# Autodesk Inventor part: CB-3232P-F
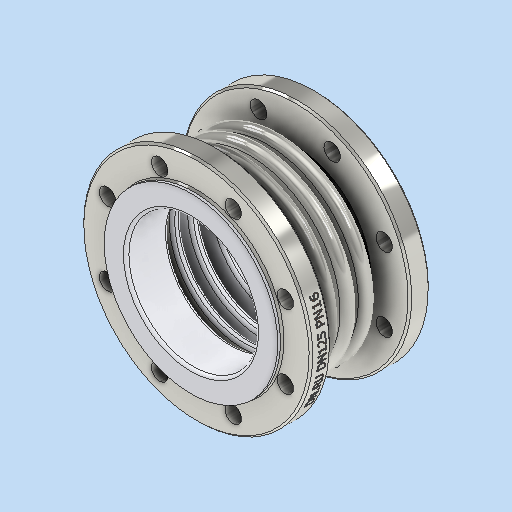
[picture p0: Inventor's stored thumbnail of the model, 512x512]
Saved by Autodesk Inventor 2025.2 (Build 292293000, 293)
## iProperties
Company: DN.RU
Created: 2026-04
Part Number: CB-3232P-F
Material: Типовые
Document SubType Name: Modeling
Designer: DN.RU
Density: 6.15933 g/cm^3
Appearance: По умолчанию
Description: D140-02142
Mass: 11200 g
Surface Area: 4913.79 cm^2
Volume: 1818.38 cm^3
Author: DN.RU
Title: Компенсатор сильфонный осевой DN.ru Ду125 Ру16
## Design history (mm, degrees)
sketch "Эскиз1"
  geometry: L1 (0, 0)-(0, -65); L2 (78.75, -65)-(78.75, 0); L3 (78.75, 0)-(0, 0); L4 (78.75, 0)-(78.75, 0); L5 (58.75, 0)-(98.75, 0); L6 (58.75, -7)-(98.75, -7); L7 (98.75, 7)-(58.75, 7); L8 (98.75, -5)-(58.75, -5); L9 (58.75, 5)-(98.75, 5); L10 (98.75, -13)-(58.75, -13); L11 (58.75, -15)-(98.75, -15); L12 (58.75, -20)-(98.75, -20); L13 (58.75, -27)-(98.75, -27); L14 (98.75, -25)-(58.75, -25); L15 (0, -65)-(78.75, -65); L16 (78.75, -65)-(70.75, -65); L17 (70.75, -65)-(70.75, -25); L18 (78.75, -15)-(76.75, -15); L19 (76.75, -15)-(76.75, -5); L20 (78.75, 5)-(76.75, 5); L21 (76.75, 5)-(76.75, 0); L22 (0, -65)-(0, -43); L23 (0, -43)-(125, -43); L24 (125, -43)-(125, -65); L25 (125, -65)-(0, -65); L26 (78.75, -43)-(78.75, -58); L27 (78.75, -58)-(82.75, -58); L28 (82.75, -58)-(82.75, -43); L29 (82.75, -43)-(78.75, -43); L30 (78.75, 0)-(105.75, 0); A1 r 7 centre (58.75, 0) between (58.75, 7) and (58.75, -7); A2 r 7 centre (98.75, 0) between (98.75, -7) and (98.75, 7); A3 r 5 centre (58.75, 0) between (58.75, 5) and (58.75, -5); A4 r 5 centre (98.75, 0) between (98.75, -5) and (98.75, 5); A5 r 5 centre (58.75, -20) between (58.75, -15) and (58.75, -25); A6 r 7 centre (58.75, -20) between (58.75, -13) and (58.75, -27); A7 r 5 centre (98.75, -20) between (98.75, -25) and (98.75, -15); A8 r 7 centre (98.75, -20) between (98.75, -27) and (98.75, -13); 20 further points
  constraints: 64 end point, 17 point on circle, 14 point on line, 8 centre point, 7 parallel, 5 perpendicular, 4 tangent, 3 midpoint, 2 vertical, 1 horizontal, 25 other
  dimensions: "d0" = 65 distance of L1.start L1.end; "d3" = 0 distance of L2.end L4.end; "d4" = 20 distance of L4.end L5.end; "d5" = 14 diameter of A2; "d6" = 2 distance between parallel lines of L6 L8; "d9" = 20 distance of L4.end point (78.75, -20); "d18" = 2 distance of L18.start L18.end; "d19" = 2 distance of L20.start L20.end; "d27" = 70.75 distance between parallel lines of L1 L17; "d28" = 8 distance between parallel lines of L2 L17; "d29" = 22 distance of L1.end L22.end; "d30" = 125 distance of L22.end L23.end; "d31" = 15 distance of L26.start L26.end; "d32" = 4 distance of L27.end L26.end
revolve "Вращение1" sketch "Эскиз1" stored, may be unused: angle "d20" = 360 deg
sketch "Эскиз3" dims "d33" = 210
  geometry: L1 (0, 0)-(71.096, 29.449); L2 (0, 0)-(76.954, 0); C1 r 9 at (97.007, 40.182); C2 r 9 at (40.182, 97.007); C3 r 9 at (-40.182, 97.007); C4 r 9 at (-97.007, 40.182); C5 r 70.75 at (0, 0) reference; C6 r 92.5 at (0, 0); C7 r 125 at (0, 0) reference; C8 r 9 at (-97.007, -40.182); C9 r 9 at (-40.182, -97.007); C10 r 9 at (40.182, -97.007); C11 r 9 at (97.007, -40.182); 1 further point
  constraints: 9 centre point, 4 end point, 2 coincident, 1 equal length, 1 horizontal, 1 point on line, 20 other
  dimensions: "d34" = 22.5 deg angle of L2 L1; "d35" = 18 diameter of C1; "d38" = 360 deg dimension on point (0, 0) C1.centre (derived); "d40" = 185 diameter of C6
  node "Эскиз — круговой массив1" dims "d38" = 360 deg (derived)
extrude "Выдавливание1" cut sketch "Эскиз3" stored distance "d41" = 10; taper "d42" = 0 deg
extrude "Выдавливание2" join sketch "Эскиз3" distance "d43" = 3; taper "d44" = 0 deg
chamfer "Фаска2" distance "d45" = 3; stored, may be unused: second distance "d46" = 2, angle "d47" = 45 deg
chamfer "Фаска3" distance "d48" = 2; stored, may be unused: second distance "d49" = 2, angle "d50" = 45 deg
mirror "Зеркальное отражение2"
fillet "Сопряжение2" dims "d51" = 3
node "РабПлоскость2"
sketch "Эскиз4"
  geometry: L1 (-60.476, 3.302)-(81.492, 3.302); L2 (81.492, 3.302)-(81.492, -37.818); L3 (81.492, -37.818)-(-60.476, -37.818); L4 (-60.476, -37.818)-(-60.476, 3.302); 1 further point
  constraints: 2 other
feature "Рельеф2" sketch "Эскиз4" dims "d3" = 0, "d52" = 0.1, "d53" = 0
sketch "Эскиз5"
  geometry: C1 r 70.75 at (0, 0) reference; C2 r 94.75 at (0, 0); 1 further point
  constraints: 1 centre point
  dimensions: "d54" = 24 radial gap between concentric circles of C1 C2
extrude "Выдавливание3" join sketch "Эскиз5" distance "d55" = 3; taper "d56" = 0 deg
fillet "Сопряжение3" dims "d57" = 3
mirror "Зеркальное отражение3"
feature "ɧ耀ɩ耀ɫ耀ɭ耀ɯ耀ɱ耀ɳ耀ɵ耀" dims "d0" = 65, "d3" = 0, "d4" = 20, "d5" = 14, "d6" = 2, "d7" = 20, "d9" = 20, "d10" = 10, "d12" = 10, "d18" = 2, "d19" = 2, "d20" = 360 deg, "d27" = 70.75, "d28" = 8, "d29" = 22, "d30" = 125, "d31" = 15, "d32" = 4, "d33" = 210, "d34" = 22.5 deg, "d35" = 18, "d36" = 80, "d38" = 360 deg (derived), "d40" = 185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
node "Твердое тело1"
node "Эскиз — прямоугольный массив1" dims "d9" = 20, "d12" = 10
